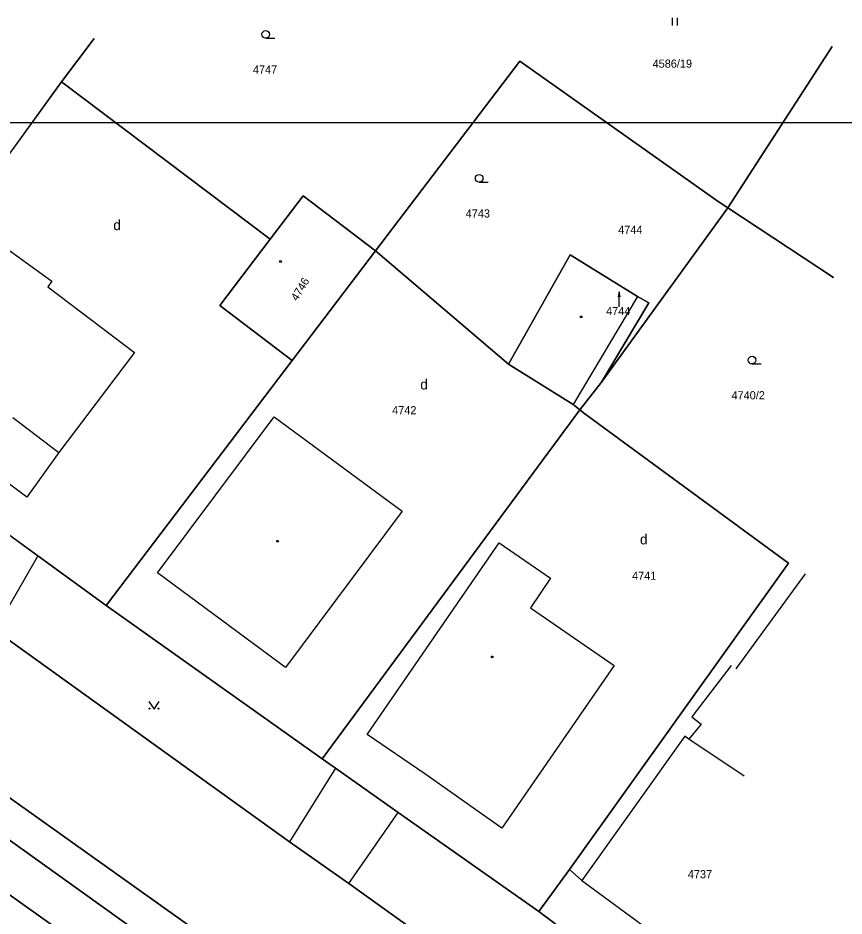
# Model space of a CAD drawing. Extents: x -400488 to -400124, y -1251493 to -1251223.
# Drawn here: x -400324.2 to -400275.7, y -1251279.7 to -1251226.9 of the extents above; entities that cross this region are included whole.
import ezdxf

# ---------------------------------------------------------------- set-up
doc = ezdxf.new("R2010")
doc.units = 0
doc.layers.add('Level 3', color=7, linetype='Continuous')
doc.layers.add('Level 63', color=7, linetype='Continuous')

msp = doc.modelspace()

# ---------------------------------------------------------------- linework, layer by layer
at = {"layer": 'Level 3'}
msp.add_lwpolyline([(-400397.431, -1251233.087), (-400250.431, -1251233.087), (-400250.431, -1251440.987), (-400397.431, -1251440.987)], close=True, dxfattribs=at)
at = {"layer": 'Level 63'}
for p, q in [((-400285.745, -1251227.385), (-400285.745, -1251226.935)), ((-400285.445, -1251227.385), (-400285.445, -1251226.935)), ((-400321.67, -1251230.69), (-400319.75, -1251228.14)), ((-400319.75, -1251228.14), (-400321.67, -1251230.69)), ((-400309.66, -1251228.13), (-400309.135, -1251228.13)), ((-400282.48, -1251238.1), (-400276.35, -1251228.62)), ((-400276.35, -1251228.62), (-400282.48, -1251238.1)), ((-400303.21, -1251240.63), (-400294.72, -1251229.47)), ((-400294.72, -1251229.47), (-400303.21, -1251240.63)), ((-400294.72, -1251229.47), (-400283.05, -1251237.72)), ((-400283.05, -1251237.72), (-400294.72, -1251229.47)), ((-400335.45, -1251249.68), (-400321.67, -1251230.69)), ((-400321.67, -1251230.69), (-400335.45, -1251249.68)), ((-400321.67, -1251230.69), (-400309.4, -1251239.95)), ((-400309.4, -1251239.95), (-400321.67, -1251230.69)), ((-400297.11, -1251236.59), (-400296.585, -1251236.59)), ((-400309.4, -1251239.95), (-400307.46, -1251237.4)), ((-400307.46, -1251237.4), (-400309.4, -1251239.95)), ((-400307.46, -1251237.4), (-400303.21, -1251240.63)), ((-400303.21, -1251240.63), (-400307.46, -1251237.4)), ((-400289.91, -1251248.35), (-400282.48, -1251238.1)), ((-400282.48, -1251238.1), (-400289.91, -1251248.35)), ((-400283.05, -1251237.72), (-400282.48, -1251238.1)), ((-400282.48, -1251238.1), (-400283.05, -1251237.72)), ((-400282.48, -1251238.1), (-400276.28, -1251242.2)), ((-400276.28, -1251242.2), (-400282.48, -1251238.1)), ((-400326.73, -1251239.16), (-400322.23, -1251242.42)), ((-400312.36, -1251243.84), (-400309.4, -1251239.95)), ((-400309.4, -1251239.95), (-400312.36, -1251243.84)), ((-400308.11, -1251247.08), (-400303.21, -1251240.63)), ((-400303.21, -1251240.63), (-400308.11, -1251247.08)), ((-400303.21, -1251240.63), (-400295.39, -1251247.3)), ((-400295.39, -1251247.3), (-400303.21, -1251240.63)), ((-400295.39, -1251247.3), (-400291.76, -1251240.86)), ((-400291.76, -1251240.86), (-400295.39, -1251247.3)), ((-400291.76, -1251240.86), (-400287.8, -1251243.32)), ((-400287.8, -1251243.32), (-400291.76, -1251240.86)), ((-400322.23, -1251242.42), (-400322.47, -1251242.75)), ((-400322.47, -1251242.75), (-400317.38, -1251246.6)), ((-400287.8, -1251243.32), (-400291.58, -1251249.67)), ((-400288.88, -1251243.03), (-400288.94, -1251243.33)), ((-400288.88, -1251243.93), (-400288.88, -1251243.03)), ((-400288.82, -1251243.33), (-400288.88, -1251243.03)), ((-400287.8, -1251243.32), (-400287.13, -1251243.69)), ((-400287.13, -1251243.69), (-400287.8, -1251243.32)), ((-400308.11, -1251247.08), (-400312.36, -1251243.84)), ((-400312.36, -1251243.84), (-400308.11, -1251247.08)), ((-400287.13, -1251243.69), (-400289.91, -1251248.35)), ((-400289.91, -1251248.35), (-400287.13, -1251243.69)), ((-400317.38, -1251246.6), (-400321.83, -1251252.48)), ((-400319.05, -1251261.49), (-400308.11, -1251247.08)), ((-400308.11, -1251247.08), (-400319.05, -1251261.49)), ((-400295.39, -1251247.3), (-400291.58, -1251249.67)), ((-400291.58, -1251249.67), (-400295.39, -1251247.3)), ((-400281.06, -1251247.28), (-400280.535, -1251247.28)), ((-400291.2, -1251249.98), (-400289.91, -1251248.35)), ((-400289.91, -1251248.35), (-400291.2, -1251249.98)), ((-400291.58, -1251249.67), (-400291.2, -1251249.98)), ((-400291.2, -1251249.98), (-400291.58, -1251249.67)), ((-400306.34, -1251270.5), (-400291.2, -1251249.98)), ((-400291.2, -1251249.98), (-400306.34, -1251270.5)), ((-400291.2, -1251249.98), (-400290.98, -1251250.15)), ((-400290.98, -1251250.15), (-400291.2, -1251249.98)), ((-400290.98, -1251250.15), (-400278.93, -1251259)), ((-400278.93, -1251259), (-400290.98, -1251250.15)), ((-400324.54, -1251250.43), (-400321.83, -1251252.48)), ((-400316.03, -1251259.56), (-400309.17, -1251250.39)), ((-400309.17, -1251250.39), (-400301.64, -1251255.93)), ((-400323.7, -1251255.12), (-400329.16, -1251251.02)), ((-400321.83, -1251252.48), (-400323.7, -1251255.12)), ((-400323.07, -1251258.57), (-400329.37, -1251253.99)), ((-400329.37, -1251253.99), (-400323.07, -1251258.57)), ((-400301.64, -1251255.93), (-400308.5, -1251265.12)), ((-400303.7, -1251269.07), (-400295.94, -1251257.8)), ((-400295.94, -1251257.8), (-400292.91, -1251259.88)), ((-400323.07, -1251258.57), (-400325.58, -1251262.94)), ((-400319.05, -1251261.49), (-400323.07, -1251258.57)), ((-400323.07, -1251258.57), (-400319.05, -1251261.49)), ((-400278.93, -1251259), (-400291.8, -1251277)), ((-400291.8, -1251277), (-400278.93, -1251259)), ((-400308.5, -1251265.12), (-400316.03, -1251259.56)), ((-400277.95, -1251259.61), (-400282.01, -1251265.21)), ((-400292.91, -1251259.88), (-400294.1, -1251261.61)), ((-400306.34, -1251270.5), (-400319.05, -1251261.49)), ((-400319.05, -1251261.49), (-400306.34, -1251270.5)), ((-400294.1, -1251261.61), (-400289.18, -1251265)), ((-400308.26, -1251275.37), (-400325.58, -1251262.94)), ((-400325.58, -1251262.94), (-400308.26, -1251275.37)), ((-400289.18, -1251265), (-400295.77, -1251274.57)), ((-400282.29, -1251265.01), (-400284.6, -1251268.02)), ((-400341.55, -1251266.53), (-400302.68, -1251294.16)), ((-400302.68, -1251294.16), (-400341.55, -1251266.53)), ((-400316.53, -1251267.12), (-400316.23, -1251267.57)), ((-400316.23, -1251267.57), (-400315.93, -1251267.12)), ((-400284.6, -1251268.02), (-400284.05, -1251268.45)), ((-400284.05, -1251268.45), (-400284.78, -1251269.34)), ((-400300.3, -1251271.37), (-400303.7, -1251269.07)), ((-400285.02, -1251269.16), (-400291.07, -1251277.65)), ((-400284.78, -1251269.34), (-400285.02, -1251269.16)), ((-400281.53, -1251271.51), (-400284.78, -1251269.34)), ((-400327.86, -1251270.56), (-400310.49, -1251282.91)), ((-400310.49, -1251282.91), (-400327.86, -1251270.56)), ((-400305.56, -1251271.05), (-400306.34, -1251270.5)), ((-400306.34, -1251270.5), (-400305.56, -1251271.05)), ((-400305.56, -1251271.05), (-400308.26, -1251275.37)), ((-400301.88, -1251273.65), (-400305.56, -1251271.05)), ((-400305.56, -1251271.05), (-400301.88, -1251273.65)), ((-400295.77, -1251274.57), (-400300.3, -1251271.37)), ((-400304.78, -1251277.83), (-400301.88, -1251273.65)), ((-400293.61, -1251279.48), (-400301.88, -1251273.65)), ((-400301.88, -1251273.65), (-400293.61, -1251279.48)), ((-400311.69, -1251284.59), (-400325.55, -1251274.7)), ((-400325.55, -1251274.7), (-400311.69, -1251284.59)), ((-400304.78, -1251277.83), (-400308.26, -1251275.37)), ((-400308.26, -1251275.37), (-400304.78, -1251277.83)), ((-400291.8, -1251277), (-400293.61, -1251279.48)), ((-400293.61, -1251279.48), (-400291.8, -1251277)), ((-400291.8, -1251277), (-400291.07, -1251277.65)), ((-400291.07, -1251277.65), (-400282.6, -1251283.85)), ((-400285.41, -1251291.65), (-400304.78, -1251277.83)), ((-400304.78, -1251277.83), (-400285.41, -1251291.65)), ((-400282.95, -1251287.38), (-400293.61, -1251279.48)), ((-400293.61, -1251279.48), (-400282.95, -1251287.38))]:
    msp.add_line(p, q, dxfattribs=at)
for centre, radius in [((-400309.66, -1251227.905), 0.225), ((-400297.11, -1251236.365), 0.225), ((-400308.79, -1251241.256), 0.054), ((-400291.12, -1251244.516), 0.054), ((-400281.06, -1251247.055), 0.225), ((-400308.96, -1251257.706), 0.054), ((-400296.34, -1251264.506), 0.054), ((-400316.5, -1251267.54), 0.03), ((-400315.96, -1251267.54), 0.03)]:
    msp.add_circle(centre, radius, dxfattribs=at)

# ---------------------------------------------------------------- texts
for s, height, p in [('4586/19', 0.48, (-400286.913, -1251229.86)), ('4747', 0.48, (-400310.416, -1251230.21)), ('4743', 0.48, (-400297.902, -1251238.67)), ('d', 0.6, (-400318.623, -1251239.41)), ('4744', 0.48, (-400288.937, -1251239.63)), ('4744', 0.48, (-400289.647, -1251244.41)), ('d', 0.6, (-400300.573, -1251248.78)), ('4740/2', 0.48, (-400282.273, -1251249.36)), ('4742', 0.48, (-400302.228, -1251250.24)), ('d', 0.6, (-400287.653, -1251257.89)), ('4741', 0.48, (-400288.119, -1251259.97)), ('4737', 0.48, (-400284.84, -1251277.52))]:
    msp.add_text(s, height=height, dxfattribs=at).set_placement(p)
msp.add_text('4746', height=0.48, rotation=58.63, dxfattribs=at).set_placement((-400307.809, -1251243.615))

doc.saveas('drawing.dxf')
